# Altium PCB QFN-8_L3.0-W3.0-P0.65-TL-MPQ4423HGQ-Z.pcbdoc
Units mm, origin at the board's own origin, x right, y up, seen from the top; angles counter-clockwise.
Board outline 16.82 x 15.87 mm, 2 copper layers (Top Layer, Bottom Layer), stack 0 mm thick; 1 components, 0 nets, 8 pads, 0 vias.
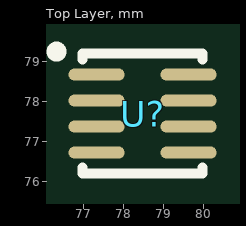
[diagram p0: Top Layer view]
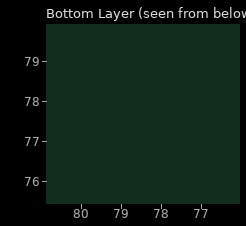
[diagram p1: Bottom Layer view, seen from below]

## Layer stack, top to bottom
Top Layer: signal copper (thickness not stored)
Bottom Layer: signal copper (thickness not stored)

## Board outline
86.674,69.85 69.85,69.85 69.85,85.723 86.674,85.723

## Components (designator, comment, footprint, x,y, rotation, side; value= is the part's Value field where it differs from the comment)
U? "" QFN-8_L3.0-W3.0-P0.65-TL-MPQ4423HGQ-Z 78.474,77.7 r0 top

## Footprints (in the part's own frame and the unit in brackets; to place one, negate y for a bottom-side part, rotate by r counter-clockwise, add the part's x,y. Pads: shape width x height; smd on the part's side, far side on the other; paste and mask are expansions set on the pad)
QFN-8_L3.0-W3.0-P0.65-TL-MPQ4423HGQ-Z [mm]
  oval 1.4x0.3 smd: 1(-1.15,0.975) 2(-1.15,0.325) 3(-1.15,-0.325) 4(-1.15,-0.975) 5(1.15,-0.975) 6(1.15,-0.325) 7(1.15,0.325) 8(1.15,0.975)
  silkscreen extent -2.27,-1.5 1.5,1.67

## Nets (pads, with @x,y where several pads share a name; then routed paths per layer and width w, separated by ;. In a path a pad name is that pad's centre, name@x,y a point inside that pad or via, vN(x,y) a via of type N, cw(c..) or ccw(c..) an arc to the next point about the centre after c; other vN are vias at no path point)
pads on no net: U?.1 U?.2 U?.3 U?.4 U?.5 U?.6 U?.7 U?.8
